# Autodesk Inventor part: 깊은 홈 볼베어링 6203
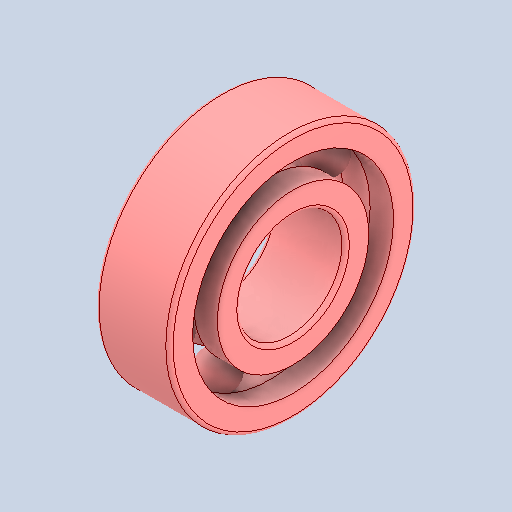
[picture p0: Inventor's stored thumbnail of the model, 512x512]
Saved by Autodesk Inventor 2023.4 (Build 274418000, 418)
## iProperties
Created: 2024-09
Part Number: 깊은 홈 볼베어링 6203
Material: 강철, 연강
Description: 깊은 그루브 볼 베어링
Document SubType Name: Modeling
Designer: EDU
Density: 7.85 g/cm^3
Appearance: 기본값
Author: jhkim
Sending System: Autodesk Inventor 2025
Preprocessor: ST-DEVELOPER v20
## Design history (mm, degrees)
feature "Solid1"
feature "Solid1:1"
feature "Solid1:2"
feature "Solid1:3"
feature "Solid1:4"
feature "Solid1:5"
feature "Solid1:6"
feature "Solid1:7"
feature "Solid1:8"
node "솔리드1"
node "솔리드2"
node "솔리드3"
node "솔리드4"
node "솔리드5"
node "솔리드6"
node "솔리드7"
node "솔리드8"
node "솔리드9"
